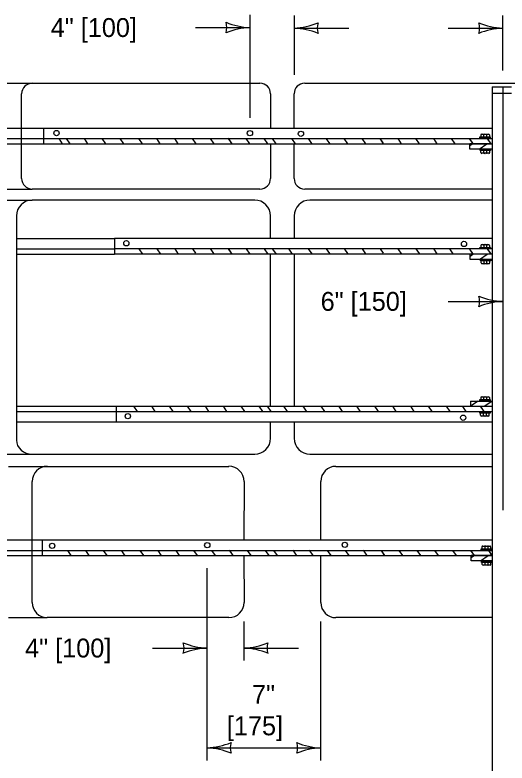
# Model space of a CAD drawing. Extents: x 49991.4 to 50021, y 49987.6 to 50011.4.
# Drawn here: x 50000.676 to 50002.239, y 49989.927 to 49992.304 of the extents above; entities that cross this region are included whole.
import ezdxf

# ---------------------------------------------------------------- set-up
doc = ezdxf.new("R2010")
doc.units = 0
for name, color, linetype in [('Level 1', 7, 'Continuous'), ('Level 2', 7, 'Continuous'), ('Level 3', 7, 'Continuous'), ('Level 4', 7, 'Continuous')]:
    doc.layers.add(name, color=color, linetype=linetype)

msp = doc.modelspace()

# ---------------------------------------------------------------- linework, layer by layer
at = {"layer": 'Level 1'}
for p, q in [((50000.7307, 49992.0873), (50001.4541, 49992.0873)), ((50001.5964, 49992.0873), (50002.3382, 49992.0873)), ((50002.192, 49992.0757), (50002.2528, 49992.0757)), ((50002.192, 49992.0757), (50002.192, 49988.4948)), ((50000.6971, 49991.7845), (50000.6971, 49992.0537)), ((50001.4878, 49992.0537), (50001.4878, 49991.9449)), ((50001.5627, 49991.9449), (50001.5627, 49992.0537)), ((50002.1922, 49992.0562), (50002.2532, 49992.0562)), ((50000.7664, 49991.9449), (50002.192, 49991.9449)), ((50000.7664, 49991.9449), (50000.7664, 49991.895)), ((50000.7664, 49991.9117), (50002.192, 49991.9117)), ((50000.815, 49991.9117), (50000.8263, 49991.895)), ((50000.8386, 49991.9117), (50000.8498, 49991.895)), ((50000.8955, 49991.9117), (50000.9068, 49991.895)), ((50000.9523, 49991.9117), (50000.9636, 49991.895)), ((50001.0091, 49991.9117), (50001.0205, 49991.895)), ((50001.0686, 49991.9117), (50001.0799, 49991.895)), ((50001.1254, 49991.9117), (50001.1366, 49991.895)), ((50001.1824, 49991.9117), (50001.1937, 49991.895)), ((50001.2392, 49991.9117), (50001.2504, 49991.895)), ((50001.296, 49991.9117), (50001.3074, 49991.895)), ((50001.3527, 49991.9123), (50001.362, 49991.8984)), ((50001.3527, 49991.9123), (50001.362, 49991.8984)), ((50001.3531, 49991.9117), (50001.3643, 49991.895)), ((50001.4098, 49991.9117), (50001.4211, 49991.895)), ((50001.4668, 49991.9117), (50001.478, 49991.895)), ((50001.4931, 49991.9117), (50001.5043, 49991.895)), ((50001.5548, 49991.9117), (50001.566, 49991.895)), ((50001.607, 49991.9117), (50001.6179, 49991.8955)), ((50001.6638, 49991.9119), (50001.6758, 49991.895)), ((50001.7207, 49991.9117), (50001.732, 49991.895)), ((50001.7776, 49991.9118), (50001.7889, 49991.895)), ((50001.8348, 49991.9114), (50001.8459, 49991.895)), ((50001.8348, 49991.9114), (50001.8442, 49991.8975)), ((50001.8348, 49991.9114), (50001.8459, 49991.895)), ((50001.8917, 49991.9113), (50001.9027, 49991.895)), ((50001.9484, 49991.9117), (50001.9596, 49991.895)), ((50002.0052, 49991.9117), (50002.0164, 49991.895)), ((50002.062, 49991.9117), (50002.0733, 49991.895)), ((50002.1191, 49991.9117), (50002.1303, 49991.895)), ((50002.1191, 49991.9117), (50002.1303, 49991.895)), ((50002.1196, 49991.9109), (50002.1289, 49991.8971)), ((50002.1554, 49991.9229), (50002.1554, 49991.9167)), ((50002.1578, 49991.9255), (50002.1805, 49991.9255)), ((50002.1579, 49991.9255), (50002.1805, 49991.9255)), ((50002.1645, 49991.9255), (50002.1645, 49991.9167)), ((50002.1738, 49991.9255), (50002.1738, 49991.9167)), ((50002.1758, 49991.9117), (50002.1871, 49991.895)), ((50002.1764, 49991.9108), (50002.1861, 49991.8965)), ((50002.1764, 49991.9108), (50002.1861, 49991.8965)), ((50002.183, 49991.9229), (50002.183, 49991.9167)), ((50000.7664, 49991.895), (50002.1212, 49991.895)), ((50001.4878, 49991.895), (50001.4878, 49991.7845)), ((50001.5627, 49991.7845), (50001.5627, 49991.895)), ((50002.1889, 49991.895), (50002.1212, 49991.895)), ((50002.1212, 49991.8889), (50002.1303, 49991.895)), ((50002.1212, 49991.895), (50002.192, 49991.895)), ((50002.1212, 49991.8782), (50002.1212, 49991.8949)), ((50002.1507, 49991.8782), (50002.1751, 49991.8948)), ((50002.192, 49991.8782), (50002.1212, 49991.8782)), ((50002.1562, 49991.867), (50002.1562, 49991.8732)), ((50002.1813, 49991.8645), (50002.1587, 49991.8645)), ((50002.1814, 49991.8645), (50002.1587, 49991.8645)), ((50002.1654, 49991.8645), (50002.1654, 49991.8732)), ((50002.1748, 49991.8645), (50002.1748, 49991.8732)), ((50002.1839, 49991.867), (50002.1839, 49991.8732)), ((50001.4541, 49991.7509), (50000.7307, 49991.7509)), ((50002.192, 49991.7508), (50001.5964, 49991.7509)), ((50001.4376, 49991.7161), (50000.731, 49991.7161)), ((50002.192, 49991.7161), (50001.6131, 49991.7161)), ((50000.6806, 49991.6656), (50000.6806, 49990.9535)), ((50001.4881, 49991.5941), (50001.4881, 49991.6656)), ((50001.5627, 49991.6656), (50001.5627, 49991.5941)), ((50000.9916, 49991.5941), (50000.9916, 49991.5441)), ((50002.1913, 49991.5941), (50000.9916, 49991.5941)), ((50002.1559, 49991.5721), (50002.1559, 49991.5659)), ((50002.1583, 49991.5746), (50002.181, 49991.5746)), ((50002.1584, 49991.5746), (50002.181, 49991.5746)), ((50002.165, 49991.5746), (50002.165, 49991.5659)), ((50002.1743, 49991.5746), (50002.1743, 49991.5659)), ((50002.1835, 49991.5721), (50002.1835, 49991.5659)), ((50002.192, 49991.5609), (50000.9916, 49991.5609)), ((50001.0695, 49991.5609), (50001.0809, 49991.5441)), ((50001.1264, 49991.5609), (50001.1377, 49991.5441)), ((50001.1833, 49991.5609), (50001.1946, 49991.5441)), ((50001.2401, 49991.5609), (50001.2495, 49991.5469)), ((50001.2963, 49991.5619), (50001.307, 49991.546)), ((50001.3536, 49991.5615), (50001.3629, 49991.5476)), ((50001.3536, 49991.5615), (50001.3629, 49991.5476)), ((50001.354, 49991.5609), (50001.3652, 49991.5441)), ((50001.4107, 49991.5609), (50001.422, 49991.5441)), ((50001.4673, 49991.5615), (50001.4791, 49991.5441)), ((50001.4944, 49991.5604), (50001.5053, 49991.5441)), ((50001.5455, 49991.56), (50001.5564, 49991.5437)), ((50001.6078, 49991.561), (50001.6187, 49991.5448)), ((50001.6647, 49991.5611), (50001.6748, 49991.5462)), ((50001.7223, 49991.56), (50001.7317, 49991.546)), ((50001.7784, 49991.561), (50001.7891, 49991.5452)), ((50001.8357, 49991.5607), (50001.845, 49991.5468)), ((50001.8357, 49991.5607), (50001.845, 49991.5468)), ((50001.8357, 49991.5607), (50001.845, 49991.5468)), ((50001.8925, 49991.5606), (50001.9034, 49991.5443)), ((50001.9494, 49991.5607), (50001.9595, 49991.5457)), ((50002.007, 49991.5595), (50002.0164, 49991.5456)), ((50002.0561, 49991.5609), (50002.0668, 49991.545)), ((50002.12, 49991.5601), (50002.1307, 49991.5441)), ((50002.12, 49991.5601), (50002.1293, 49991.5462)), ((50002.12, 49991.5601), (50002.1293, 49991.5462)), ((50002.1762, 49991.5609), (50002.1876, 49991.5441)), ((50002.1768, 49991.56), (50002.1865, 49991.5457)), ((50002.1768, 49991.56), (50002.1865, 49991.5457)), ((50002.1217, 49991.5441), (50000.9916, 49991.5441)), ((50001.4881, 49991.0608), (50001.4881, 49991.5441)), ((50001.5627, 49991.5441), (50001.5627, 49991.0608)), ((50002.1894, 49991.5441), (50002.1217, 49991.5441)), ((50002.1217, 49991.5381), (50002.1307, 49991.5441)), ((50002.192, 49991.5441), (50002.1217, 49991.5441)), ((50002.1217, 49991.5274), (50002.1217, 49991.544)), ((50002.192, 49991.5274), (50002.1217, 49991.5274)), ((50002.1512, 49991.5274), (50002.1756, 49991.5439)), ((50002.1567, 49991.5162), (50002.1567, 49991.5224)), ((50002.1818, 49991.5136), (50002.1592, 49991.5136)), ((50002.1819, 49991.5136), (50002.1592, 49991.5136)), ((50002.1659, 49991.5136), (50002.1659, 49991.5224)), ((50002.1752, 49991.5136), (50002.1752, 49991.5224)), ((50002.1843, 49991.5162), (50002.1843, 49991.5224)), ((50002.1226, 49991.0768), (50002.1226, 49991.0608)), ((50002.1226, 49991.0768), (50002.192, 49991.0768)), ((50002.147, 49991.0768), (50002.1232, 49991.0608)), ((50002.1553, 49991.0881), (50002.1553, 49991.082)), ((50002.1577, 49991.0907), (50002.1805, 49991.0907)), ((50002.1578, 49991.0907), (50002.1805, 49991.0907)), ((50002.1644, 49991.0907), (50002.1644, 49991.082)), ((50002.192, 49991.0767), (50002.1686, 49991.0608)), ((50002.1737, 49991.0907), (50002.1737, 49991.082)), ((50002.1829, 49991.0881), (50002.1829, 49991.082)), ((50000.9973, 49991.0608), (50000.9973, 49991.0108)), ((50000.9973, 49991.0608), (50002.1226, 49991.0608)), ((50001.0524, 49991.0608), (50001.0637, 49991.0441)), ((50001.1093, 49991.0608), (50001.1205, 49991.0441)), ((50001.1662, 49991.0608), (50001.1776, 49991.0441)), ((50001.2229, 49991.0611), (50001.2343, 49991.0441)), ((50001.2799, 49991.0608), (50001.2911, 49991.0441)), ((50001.3369, 49991.0608), (50001.3482, 49991.0441)), ((50001.3936, 49991.0608), (50001.4049, 49991.0441)), ((50001.4506, 49991.0608), (50001.4619, 49991.0441)), ((50001.4771, 49991.0606), (50001.4882, 49991.0441)), ((50001.5294, 49991.0608), (50001.5407, 49991.0441)), ((50001.5905, 49991.0612), (50001.6014, 49991.045)), ((50001.6474, 49991.0613), (50001.6591, 49991.0441)), ((50001.705, 49991.0602), (50001.7158, 49991.0441)), ((50001.7611, 49991.0612), (50001.7719, 49991.0454)), ((50001.8184, 49991.0609), (50001.8296, 49991.0441)), ((50001.8184, 49991.0609), (50001.8277, 49991.047)), ((50001.8184, 49991.0609), (50001.8277, 49991.047)), ((50001.8752, 49991.0608), (50001.8861, 49991.0446)), ((50001.9321, 49991.0608), (50001.9431, 49991.0446)), ((50001.9889, 49991.0608), (50001.9999, 49991.0446)), ((50002.0458, 49991.0608), (50002.0571, 49991.0441)), ((50002.0977, 49991.0601), (50002.1085, 49991.0441)), ((50002.0977, 49991.0601), (50002.1086, 49991.044)), ((50002.1226, 49991.0608), (50002.192, 49991.0608)), ((50002.154, 49991.0608), (50002.1653, 49991.0441)), ((50002.1545, 49991.0601), (50002.1654, 49991.044)), ((50002.1545, 49991.0601), (50002.1654, 49991.044)), ((50002.1545, 49991.0601), (50002.1654, 49991.044)), ((50002.1545, 49991.0601), (50002.1654, 49991.044)), ((50002.1545, 49991.0601), (50002.1654, 49991.044)), ((50000.9973, 49991.0441), (50002.192, 49991.0441)), ((50002.1551, 49991.0322), (50002.1551, 49991.0383)), ((50002.1802, 49991.0296), (50002.1576, 49991.0296)), ((50002.1803, 49991.0296), (50002.1576, 49991.0296)), ((50002.1643, 49991.0296), (50002.1643, 49991.0383)), ((50002.1736, 49991.0296), (50002.1736, 49991.0383)), ((50002.1827, 49991.0322), (50002.1827, 49991.0383)), ((50000.9973, 49991.0108), (50002.1902, 49991.0108)), ((50001.4881, 49990.959), (50001.4881, 49991.0108)), ((50001.5627, 49991.0108), (50001.5627, 49990.959)), ((50000.731, 49990.9086), (50001.4376, 49990.9086)), ((50001.6131, 49990.9086), (50002.192, 49990.9086)), ((50000.7786, 49990.8698), (50001.3554, 49990.8698)), ((50001.6954, 49990.8697), (50002.192, 49990.8697)), ((50000.7305, 49990.4372), (50000.7305, 49990.8218)), ((50001.4035, 49990.8218), (50001.4034, 49990.6361)), ((50001.6473, 49990.6361), (50001.6473, 49990.8216)), ((50000.7624, 49990.6361), (50000.7624, 49990.5861)), ((50000.7624, 49990.6361), (50002.1909, 49990.6361)), ((50000.7624, 49990.6029), (50002.192, 49990.6029)), ((50000.8425, 49990.6029), (50000.8538, 49990.5861)), ((50000.8995, 49990.6029), (50000.9105, 49990.5866)), ((50000.9563, 49990.6029), (50000.9674, 49990.5864)), ((50001.0141, 49990.6014), (50001.0249, 49990.5856)), ((50001.0726, 49990.6029), (50001.0839, 49990.5861)), ((50001.1294, 49990.6029), (50001.1397, 49990.5876)), ((50001.1864, 49990.6029), (50001.1978, 49990.5861)), ((50001.2433, 49990.6028), (50001.2545, 49990.5861)), ((50001.3, 49990.6029), (50001.3115, 49990.5861)), ((50001.3567, 49990.6034), (50001.366, 49990.5896)), ((50001.3567, 49990.6034), (50001.366, 49990.5896)), ((50001.357, 49990.6029), (50001.3684, 49990.5861)), ((50001.4138, 49990.6029), (50001.4251, 49990.5861)), ((50001.4707, 49990.6029), (50001.4821, 49990.5861)), ((50001.4971, 49990.6029), (50001.5084, 49990.5861)), ((50001.5584, 49990.6034), (50001.5693, 49990.5872)), ((50001.6109, 49990.603), (50001.6219, 49990.5867)), ((50001.6679, 49990.6029), (50001.6792, 49990.5861)), ((50001.7247, 49990.6029), (50001.7361, 49990.5861)), ((50001.7815, 49990.603), (50001.7923, 49990.5871)), ((50001.8388, 49990.6026), (50001.8498, 49990.5861)), ((50001.8388, 49990.6026), (50001.8481, 49990.5887)), ((50001.8388, 49990.6026), (50001.8481, 49990.5887)), ((50001.8956, 49990.6025), (50001.9066, 49990.5862)), ((50001.9525, 49990.6026), (50001.9637, 49990.5861)), ((50002.0091, 49990.6029), (50002.0204, 49990.5861)), ((50002.0663, 49990.6025), (50002.077, 49990.5866)), ((50002.123, 49990.6029), (50002.1343, 49990.5861)), ((50002.1235, 49990.6021), (50002.1329, 49990.5882)), ((50002.1235, 49990.6021), (50002.1329, 49990.5882)), ((50002.1594, 49990.6141), (50002.1594, 49990.6079)), ((50002.1618, 49990.6166), (50002.1845, 49990.6166)), ((50002.1619, 49990.6166), (50002.1845, 49990.6166)), ((50002.1685, 49990.6166), (50002.1685, 49990.6079)), ((50002.1778, 49990.6166), (50002.1778, 49990.6079)), ((50002.1804, 49990.602), (50002.1912, 49990.5861)), ((50002.1804, 49990.602), (50002.1901, 49990.5877)), ((50002.1804, 49990.602), (50002.1901, 49990.5877)), ((50002.187, 49990.6141), (50002.187, 49990.6079)), ((50000.7624, 49990.5861), (50002.1252, 49990.5861)), ((50001.4034, 49990.5861), (50001.4035, 49990.4372)), ((50001.6473, 49990.4371), (50001.6473, 49990.5861)), ((50002.1252, 49990.5801), (50002.1343, 49990.5861)), ((50002.1252, 49990.5694), (50002.1252, 49990.5861)), ((50002.192, 49990.5861), (50002.1252, 49990.5861)), ((50002.1252, 49990.5861), (50002.1913, 49990.5861)), ((50002.1546, 49990.5693), (50002.1791, 49990.586)), ((50002.1916, 49990.5694), (50002.1252, 49990.5694)), ((50002.1602, 49990.5582), (50002.1602, 49990.5644)), ((50002.1853, 49990.5557), (50002.1627, 49990.5557)), ((50002.1854, 49990.5557), (50002.1627, 49990.5557)), ((50002.1694, 49990.5557), (50002.1694, 49990.5644)), ((50002.1787, 49990.5557), (50002.1787, 49990.5644)), ((50002.1879, 49990.5582), (50002.1879, 49990.5644)), ((50001.3554, 49990.3892), (50000.7786, 49990.3892)), ((50002.192, 49990.3891), (50001.6954, 49990.3891))]:
    msp.add_line(p, q, dxfattribs=at)
for points in [[(50002.1526, 49991.9119), (50002.1526, 49991.9165), (50002.1855, 49991.9165), (50002.1855, 49991.9119)], [(50002.1866, 49991.8781), (50002.1866, 49991.8734), (50002.1538, 49991.8734), (50002.1538, 49991.8781)], [(50002.1531, 49991.561), (50002.1531, 49991.5657), (50002.186, 49991.5657), (50002.186, 49991.561)], [(50002.1871, 49991.5272), (50002.1871, 49991.5226), (50002.1542, 49991.5226), (50002.1542, 49991.5272)], [(50002.1525, 49991.0771), (50002.1525, 49991.0818), (50002.1854, 49991.0818), (50002.1854, 49991.0771)], [(50002.1855, 49991.0432), (50002.1855, 49991.0385), (50002.1526, 49991.0385), (50002.1526, 49991.0432)], [(50002.1566, 49990.6031), (50002.1566, 49990.6077), (50002.1895, 49990.6077), (50002.1895, 49990.6031)], [(50002.1906, 49990.5692), (50002.1906, 49990.5646), (50002.1577, 49990.5646), (50002.1577, 49990.5692)]]:
    msp.add_lwpolyline(points, close=True, dxfattribs=at)
for centre in [(50000.8078, 49991.9289), (50001.4224, 49991.9286), (50001.5844, 49991.9266), (50001.0297, 49991.5788), (50002.1023, 49991.5767), (50001.0344, 49991.0293), (50002.0998, 49991.0244), (50000.794, 49990.6173), (50001.2867, 49990.6193), (50001.7236, 49990.6204)]:
    msp.add_circle(centre, 0.00843, dxfattribs=at)
for centre, radius, start, end in [((50000.7307, 49992.0537), 0.0336, 90, 180), ((50001.4541, 49992.0537), 0.0336, 0, 90), ((50001.5964, 49992.0537), 0.0336, 90, 180), ((50002.158, 49991.9229), 0.00257, 90, 180), ((50002.162, 49991.9229), 0.00257, 0, 90), ((50002.1672, 49991.9229), 0.00257, 90, 180), ((50002.1712, 49991.9229), 0.00257, 0, 90), ((50002.1764, 49991.9229), 0.00257, 90, 180), ((50002.1804, 49991.9229), 0.00257, 0, 90), ((50002.1588, 49991.867), 0.00257, 180, 270), ((50002.1629, 49991.867), 0.00257, 270, 0), ((50002.168, 49991.867), 0.00257, 180, 270), ((50002.1721, 49991.867), 0.00257, 270, 0), ((50002.1772, 49991.867), 0.00257, 180, 270), ((50002.1813, 49991.867), 0.00257, 270, 0), ((50000.7307, 49991.7845), 0.0336, 180, 270), ((50001.4541, 49991.7845), 0.0336, 270, 0), ((50001.5964, 49991.7845), 0.0336, 180, 270), ((50000.731, 49991.6656), 0.0505, 90, 180), ((50001.4376, 49991.6656), 0.0505, 0, 90), ((50001.6131, 49991.6656), 0.0505, 90, 180), ((50002.1584, 49991.5721), 0.00257, 90, 180), ((50002.1625, 49991.5721), 0.00257, 0, 90), ((50002.1676, 49991.5721), 0.00257, 90, 180), ((50002.1717, 49991.5721), 0.00257, 0, 90), ((50002.1769, 49991.5721), 0.00257, 90, 180), ((50002.1809, 49991.5721), 0.00257, 0, 90), ((50002.1593, 49991.5162), 0.00257, 180, 270), ((50002.1633, 49991.5162), 0.00257, 270, 0), ((50002.1685, 49991.5162), 0.00257, 180, 270), ((50002.1726, 49991.5162), 0.00257, 270, 0), ((50002.1777, 49991.5162), 0.00257, 180, 270), ((50002.1818, 49991.5162), 0.00257, 270, 0), ((50002.1579, 49991.0882), 0.00257, 90, 180), ((50002.1619, 49991.0882), 0.00257, 0, 90), ((50002.1671, 49991.0882), 0.00257, 90, 180), ((50002.1711, 49991.0882), 0.00257, 0, 90), ((50002.1763, 49991.0882), 0.00257, 90, 180), ((50002.1804, 49991.0882), 0.00257, 0, 90), ((50002.1577, 49991.0321), 0.00257, 180, 270), ((50002.1617, 49991.0321), 0.00257, 270, 0), ((50002.1669, 49991.0321), 0.00257, 180, 270), ((50002.1709, 49991.0321), 0.00257, 270, 0), ((50002.1761, 49991.0321), 0.00257, 180, 270), ((50002.1801, 49991.0321), 0.00257, 270, 0), ((50001.4376, 49990.959), 0.0505, 270, 0), ((50001.6131, 49990.959), 0.0505, 180, 270), ((50000.7786, 49990.8218), 0.0481, 90, 180), ((50001.3554, 49990.8218), 0.0481, 0, 90), ((50001.6954, 49990.8217), 0.0481, 90, 180), ((50002.162, 49990.6141), 0.00257, 90, 180), ((50002.166, 49990.6141), 0.00257, 0, 90), ((50002.1712, 49990.6141), 0.00257, 90, 180), ((50002.1752, 49990.6141), 0.00257, 0, 90), ((50002.1804, 49990.6141), 0.00257, 90, 180), ((50002.1844, 49990.6141), 0.00257, 0, 90), ((50002.1628, 49990.5582), 0.00257, 180, 270), ((50002.1669, 49990.5582), 0.00257, 270, 0), ((50002.172, 49990.5582), 0.00257, 180, 270), ((50002.1761, 49990.5582), 0.00257, 270, 0), ((50002.1812, 49990.5582), 0.00257, 180, 270), ((50002.1853, 49990.5582), 0.00257, 270, 0), ((50000.7786, 49990.4372), 0.0481, 180, 270), ((50001.3554, 49990.4372), 0.0481, 270, 0), ((50001.6954, 49990.4371), 0.0481, 180, 270)]:
    msp.add_arc(centre, radius, start, end, dxfattribs=at)
msp.add_ellipse((50000.731, 49990.9535), major_axis=(-0.0505, 0), ratio=0.891022, start_param=0, end_param=1.570796, dxfattribs=at)
at = {"layer": 'Level 3'}
for p, q in [((50001.4224, 49992.3042), (50001.4224, 49991.977)), ((50001.5627, 49992.3023), (50001.5627, 49992.1137)), ((50002.2253, 49992.1273), (50002.2253, 49992.3023)), ((50001.249, 49992.2642), (50001.4224, 49992.2642)), ((50001.5627, 49992.2623), (50001.7361, 49992.2623)), ((50002.0519, 49992.2623), (50002.2253, 49992.2623)), ((50002.0519, 49991.394), (50002.2253, 49991.394)), ((50001.2864, 49990.4413), (50001.2864, 49990.5461)), ((50001.2864, 49989.9352), (50001.2864, 49990.4413)), ((50001.4035, 49990.2524), (50001.4035, 49990.3772)), ((50001.6473, 49989.9352), (50001.6473, 49990.3771)), ((50001.113, 49990.2924), (50001.2864, 49990.2924)), ((50001.4035, 49990.2924), (50001.5769, 49990.2924)), ((50001.2864, 49989.9752), (50001.6473, 49989.9752))]:
    msp.add_line(p, q, dxfattribs=at)
for centre, radius, start, end in [((50001.4316, 49992.4863), 0.2223, 247.456, 267.6395), ((50001.2942, 49992.2642), 0.0548, 342.1388, 17.8612), ((50001.4339, 49992.0315), 0.233, 92.8273, 112.0772), ((50001.5512, 49992.495), 0.233, 272.8273, 292.0772), ((50001.5535, 49992.0402), 0.2223, 67.456, 87.6395), ((50001.6909, 49992.2623), 0.0548, 162.1388, 197.8612), ((50002.2345, 49992.4844), 0.2223, 247.456, 267.6395), ((50002.0971, 49992.2623), 0.0548, 342.1388, 17.8612), ((50002.2368, 49992.0296), 0.233, 92.8273, 112.0772), ((50002.2345, 49991.6161), 0.2223, 247.456, 267.6395), ((50002.0971, 49991.394), 0.0548, 342.1388, 17.8612), ((50002.2368, 49991.1613), 0.233, 92.8273, 112.0772), ((50001.2956, 49990.5145), 0.2223, 247.456, 267.6395), ((50001.1582, 49990.2924), 0.0548, 342.1388, 17.8612), ((50001.2979, 49990.0597), 0.233, 92.8273, 112.0772), ((50001.392, 49990.5251), 0.233, 272.8273, 292.0772), ((50001.3943, 49990.0703), 0.2223, 67.456, 87.6395), ((50001.5317, 49990.2924), 0.0548, 162.1388, 197.8612), ((50001.2749, 49990.2079), 0.233, 272.8273, 292.0772), ((50001.4146, 49989.9752), 0.0548, 162.1388, 197.8612), ((50001.6565, 49990.1973), 0.2223, 247.456, 267.6395), ((50001.5191, 49989.9752), 0.0548, 342.1388, 17.8612), ((50001.2773, 49989.7531), 0.2223, 67.456, 87.6395), ((50001.6588, 49989.7425), 0.233, 92.8273, 112.0772)]:
    msp.add_arc(centre, radius, start, end, dxfattribs=at)
at = {"layer": 'Level 4'}
for p, q in [((50000.6202, 49992.0873), (50000.7307, 49992.0873)), ((50002.2253, 49992.0733), (50002.2253, 49990.7306)), ((50000.6291, 49991.9449), (50000.7664, 49991.9449)), ((50000.6291, 49991.9117), (50000.7664, 49991.9117)), ((50000.6291, 49991.895), (50000.7664, 49991.895)), ((50000.6201, 49991.7509), (50000.7307, 49991.7509)), ((50000.6202, 49991.7161), (50000.731, 49991.7161)), ((50000.6806, 49991.5942), (50000.6806, 49991.5442)), ((50000.6806, 49991.5942), (50000.9916, 49991.5942)), ((50000.6806, 49991.5609), (50000.9916, 49991.5609)), ((50000.6806, 49991.5442), (50000.9916, 49991.5442)), ((50000.6806, 49991.0608), (50000.6806, 49991.0108)), ((50000.6806, 49991.0608), (50000.9973, 49991.0608)), ((50000.6806, 49991.0441), (50000.9973, 49991.0441)), ((50000.6806, 49991.0108), (50000.9973, 49991.0108)), ((50000.6202, 49990.9086), (50000.731, 49990.9086)), ((50000.6553, 49990.8698), (50000.7786, 49990.8698)), ((50000.6291, 49990.6361), (50000.7624, 49990.6361)), ((50000.6291, 49990.6029), (50000.7624, 49990.6029)), ((50000.6291, 49990.5861), (50000.7624, 49990.5861)), ((50000.6553, 49990.3892), (50000.7786, 49990.3892))]:
    msp.add_line(p, q, dxfattribs=at)

# ---------------------------------------------------------------- texts
at = {"layer": 'Level 2'}
for s, p in [('4" [100]', (50000.7895, 49992.2342)), ('6" [150]', (50001.6469, 49991.364)), ('4" [100]', (50000.7081, 49990.2624)), ('7"', (50001.4289, 49990.1152)), ('[175]', (50001.349, 49990.0152))]:
    msp.add_text(s, height=0.06, dxfattribs=at).set_placement(p)

doc.saveas('drawing.dxf')
